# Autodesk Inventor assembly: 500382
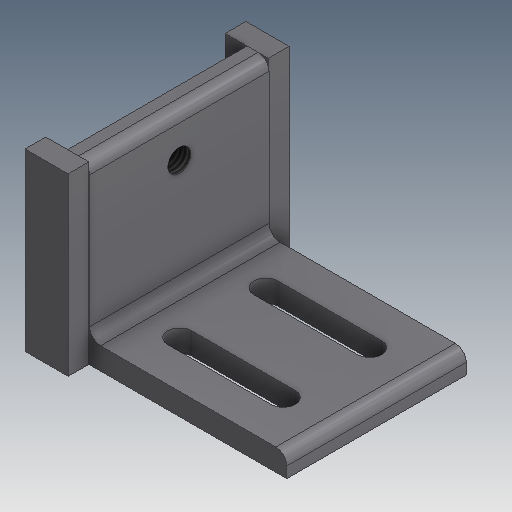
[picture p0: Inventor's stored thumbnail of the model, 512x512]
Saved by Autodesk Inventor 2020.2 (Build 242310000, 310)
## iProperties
Created: 1999-12
Part Number: 500382
Description: WMT-FA,AH,CP,BRACKET,MNT,SIDE_GUIDE
Document SubType Name: Assembly
Designer: sspink
Mass: 312.643 g
Surface Area: 172.11 cm^2
Volume: 39.7765 cm^3
Density: 7.86 g/cm^3
Control State: 0
Checked Out: False
Last Check In By: gpurviance
Last Check In Date: 2000-01-06
Master: False
Shininess: 0.0
Length Units: 11269
Angle Units: 11279
Time Units: 11290
Mass Units: 11283
Length Display Precision: 3
Angle Display Precision: 2
Compacted: True
Dimensions: 50,8x64x69,9 mm
Mass: 0,313 kg
Density: 0.0
Volumn: 0.0
Area: 0.0
PropertySet Name: Model Information
Author: sspink
Revision Number: -
Title: WMT-FA,AH,CP,BRACKET,MNT,SIDE_GUIDE
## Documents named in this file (3)
- D:\07 - DEMODATEN\OTX 2019 - Dataset - UPDATE - Dez2019\Designs\07-Packing machine\500382.iam
- D:\07 - DEMODATEN\OTX 2019 - Dataset - UPDATE - Dez2019\Designs\07-Packing machine\Parts\ADSK-011369.ipt
- D:\07 - DEMODATEN\OTX 2019 - Dataset - UPDATE - Dez2019\Designs\07-Packing machine\Parts\ADSK-011368.ipt
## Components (3 placed, 2 different names)
1. ADSK-011368:1 — Flush:1, Flush:2, Flush:3, Flush:4, Mate:1, Mate:2
2. ADSK-011369:1 — Flush:1, Flush:2, Mate:1
3. ADSK-011369:2 — Flush:3, Flush:4, Mate:2
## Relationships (6: Flush 4, Mate 2)
- Flush:1: ADSK-011368:1 ↔ ADSK-011369:1
- Flush:2: ADSK-011368:1 ↔ ADSK-011369:1
- Flush:3: ADSK-011368:1 ↔ ADSK-011369:2
- Flush:4: ADSK-011368:1 ↔ ADSK-011369:2
- Mate:1: ADSK-011368:1 ↔ ADSK-011369:1
- Mate:2: ADSK-011368:1 ↔ ADSK-011369:2
